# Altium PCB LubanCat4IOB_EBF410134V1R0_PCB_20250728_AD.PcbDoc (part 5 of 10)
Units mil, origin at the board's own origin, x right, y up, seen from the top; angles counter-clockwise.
Board outline 5236.21 x 4055.11 mil, 6 copper layers (TOP, GND02, ART03, PWR04, GND05, BOTTOM), stack 47.2 mil thick; 614 components, 490 nets, 2311 pads, 1916 vias.
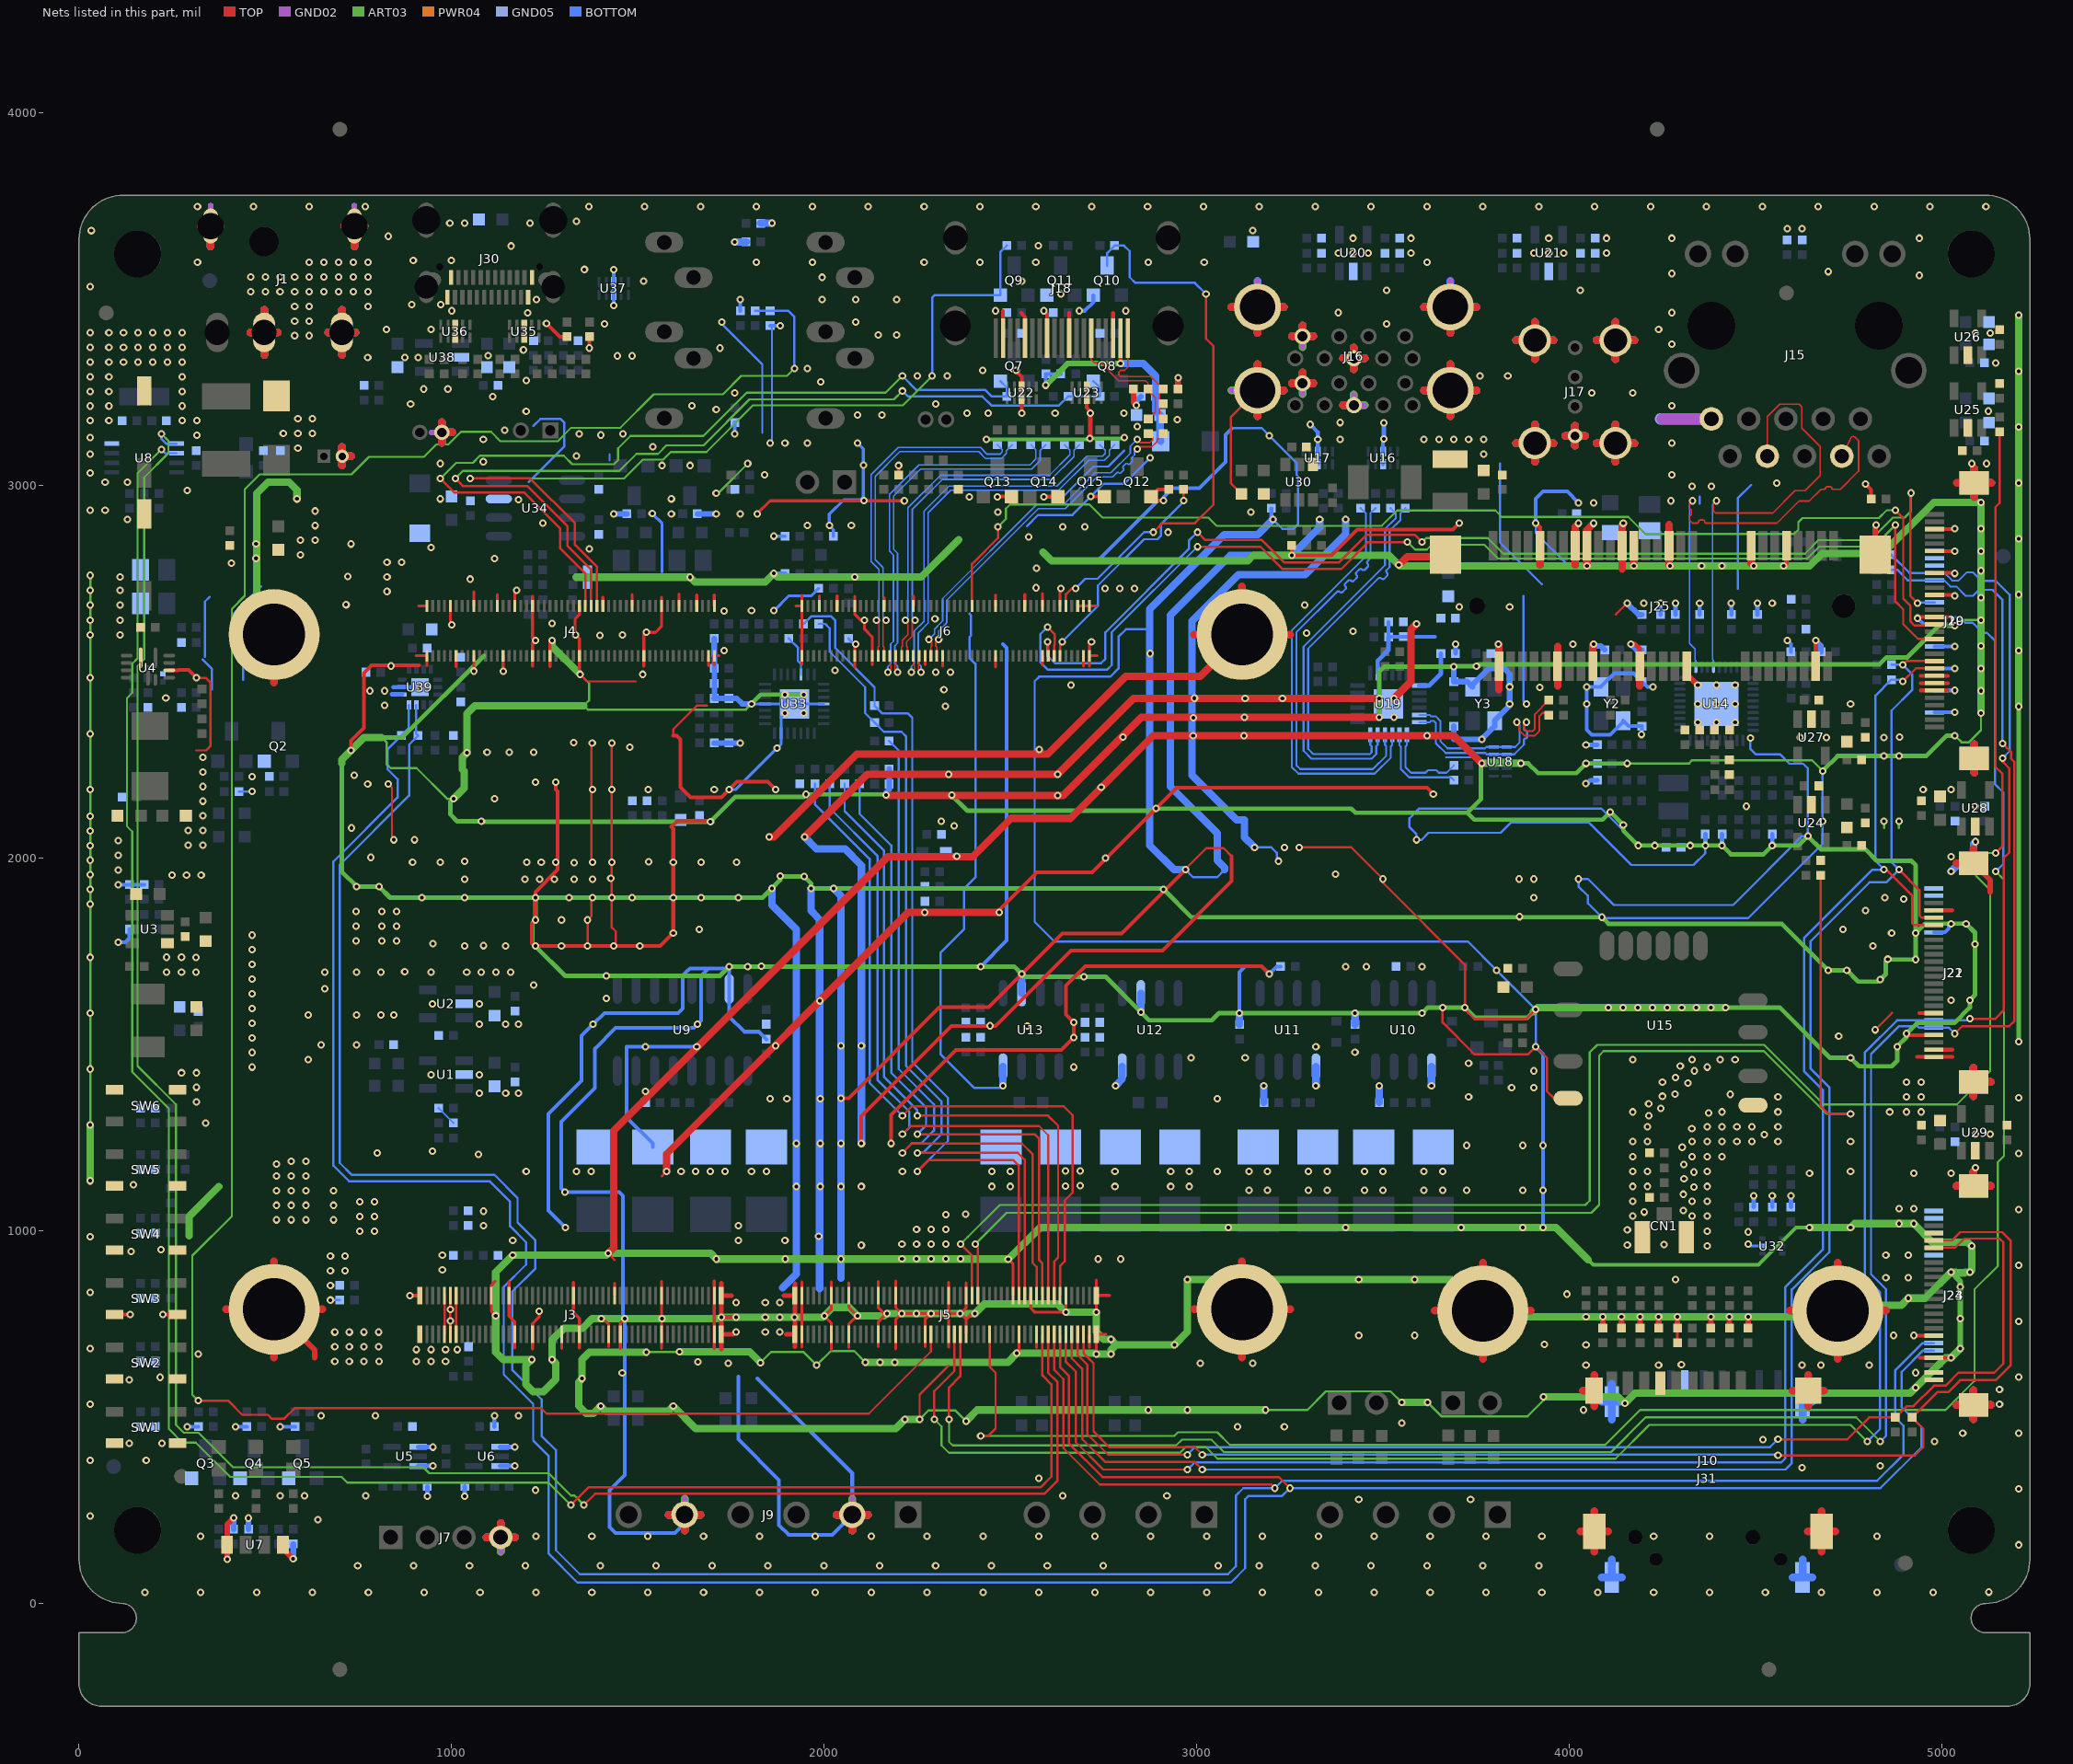
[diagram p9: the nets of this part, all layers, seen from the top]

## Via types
v1: diameter 20, hole 10, TOP to BOTTOM, 1912 vias
v2: diameter 40/50/50/50/50/40 (per signal layer), hole 0, TOP to BOTTOM, 4 vias

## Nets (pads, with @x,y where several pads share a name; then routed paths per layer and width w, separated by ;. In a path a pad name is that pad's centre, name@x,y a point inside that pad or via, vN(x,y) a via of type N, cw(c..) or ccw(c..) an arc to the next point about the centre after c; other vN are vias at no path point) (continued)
GND: (continued)
  BOTTOM w12: 839.68,2439.68 U39.8@867.36,2439.68 ; 844,2459.37 U39.9@867.36,2459.37 v1(915,2459.37) ; U5.3@910.43,369.09 949.72,369.09 v1(950,369.37) ; U5.1@910.43,420.28 949.09,420.28 v1(950,419.37) ; v1(934.68,287.57) Z3.2@934.68,314.37 ; v1(1035.32,287.57) Z4.2@1035.32,314.37 ; C42.2@1114.68,474.37 1114.68,504.05 v1(1115,504.37) ; U6.3@1130.43,369.09 1169.72,369.09 v1(1170,369.37) ; U6.1@1130.43,420.28 1169.41,420.28 v1(1170,419.69) ; v1(3502,3125.37) v1(3502,3168.37) ; v1@3620,534.07 v1(3620,539.37) ; C112.2@3694.68,2549.37 3694.68,2574.05 v1(3695,2574.37) ; v1(4044,2200.37) 4047,2200.37 4056,2209.37 R103.2@4075.32,2209.37 ; v1(4045,2254.37) R102.2@4075.32,2254.37 ; v1(4045,2304.37) R98.2@4075.32,2304.37 ; R86.2@4245,2654.05 v1(4245,2684.37) ; C88.2@4285,2654.05 v1(4285,2684.37) ; C84.2@4350,2654.05 v1(4350,2684.37) ; v1(4365,2034.37) R83.2@4365,2064.69 ; v1(4410,2034.37) R92.2@4410,2064.69 ; C83.2@4435,2654.05 v1(4435,2684.37) ; C155.2@4495,1064.05 v1(4495,1094.37) ; C89.2@4505,2654.05 v1(4505,2684.37) ; C153.2@4545,1064.05 v1(4545,1094.37) ; v1(4545,2034.37) R91.2@4545,2064.69 ; C154.2@4595,1064.05 v1(4595,1094.37)
  BOTTOM w15: C48.2@415,199.05 v1(415,229.37) ; C47.2@455,199.05 v1(455,229.15) ; v1(575,119.37) C46.2@575,159.69 ; v1(1435,2924.37) R215.1@1470.32,2924.37 ; R211.1@1659.68,2924.37 v1(1710,2924.37) ; C169.2@1705,2309.69 C168.2@1745,2309.69 1774.68,2309.69 v1(1775,2309.37) ; R234.1@1705,2589.69 1705,2544.37 1705.32,2544.05 C180.2@1705.32,2509.37 C181.2@1705.32,2469.37 1705.32,2429.37 C167.2@1705,2429.05 C166.2@1745,2429.05 1765.32,2429.05 1780,2414.37 v1(1805,2414.37) ; v1(2166,2169.37) 2166,2175.37 2174.68,2184.05 C174.2@2174.68,2199.37 C175.2@2174.68,2239.37 ; v1(2838,3215.37) 2838,3227.05 D34.1@2850.32,3239.37 ; C102.1@3690,2354.69 3690,2319.37 v1(3765,2319.37) 3799.53,2353.9 Y3.2@3799.53,2369.09 3840,2409.57 v1(3840,2414.37) v1(3840,2460.37) 3840,2494.37 3825,2509.37 3784.88,2509.37 3740.47,2464.96 Y3.4@3740.47,2459.65 3726.07,2474.05 C103.2@3690,2474.05 v1(3690,2514.37) ; v1(4065,2574.37) 4070,2569.37 4085.32,2569.37 C86.2@4095.32,2559.37 ; v1(4155,2684.37) 4185.32,2654.05 C160.2@4195,2654.05 ; v1(4165,2574.37) 4180.32,2559.05 C85.2@4195,2559.05 ; v1(4661.56,2584.37) 4675.32,2570.61 C158.2@4675.32,2554.37
  BOTTOM w20: v1(1760,3654.37) R219.2@1790.32,3654.37 ; R217.2@1829.68,3704.37 v1(1860,3704.37) ; v1(1860,1919.37) 1860,1874.37 1925,1809.37 v1(1925,1234.37) v1(1925,1119.37) 1925,884.37 1888,847.37 ; v1(1947.5,2056.87) 1979.05,2025.32 2055.85,2025.32 2100,1981.17 v1(2100,1496.37) v1(2100,1234.37) ; v1(1965,1919.37) 1965,1859.37 1980,1844.37 1980,1843.18 1987.8,1835.38 1987.8,844.37 ; v1(2025,1919.37) 2045,1899.37 v1(2045,1496.37) v1(2045,1356.37) v1(2045,1234.37) v1(2045,1119.37) v1(2045,924.37) 2045,872.65 ; v1(2480,1389.37) U13.8@2480,1440.94 ; U13.2@2530,1637.8 v1(2530,1689.37) ; v1(2782.31,1389.37) 2800,1407.06 U12.8@2800,1440.94 ; v1(2850,1587.36) U12.2@2850,1637.8 ; v1(2970,1969.37) 2939,1969.37 2874,2034.37 2874,2614.37 2874,2668.37 3074,2868.37 3164,2868.37 v1(3205,2909.37) ; 3075,1969.37 3075,1974.37 3055,1994.37 3055,2067.14 2929.65,2192.49 2929.65,2652.25 3090.29,2812.89 v1(3255,2812.89) 3330,2887.89 v1(3330,2909.37) ; C61.2@3115,1554.05 v1(3115,1584.37) ; v1(3155,2029.37) 3128.05,2056.32 3128.05,2103.37 3107.38,2103.37 2987.65,2223.1 2987.65,2636.02 3112.35,2760.72 3291.35,2760.72 3400,2869.37 v1(3400,2909.37) ; R72.2@3180.32,1344.37 v1(3180.32,1389.37) ; v1(3320,1389.37) U11.5@3320,1440.94 ; C60.2@3425,1554.05 v1(3425,1584.37) ; R64.2@3490.32,1344.37 v1(3490.32,1389.37) ; v1@3589.68,2629.05 v1(3590,2629.37) ; v1(3630,1389.37) U10.5@3630,1440.94 ; 4280.24,3179.13 J15.10@4381.49,3179.13 ; v1(5025,1964.37) 5046.85,1986.22 J21.25@5084.99,1986.22 5084.99,2039.36 v1(5090,2044.37)
  BOTTOM w21: 326.66,3696.82 J1.1@353.36,3696.82 ; 353.36,3642.57 J1.1@353.36,3696.82 ; 380.06,3696.82 J1.1@353.36,3696.82 ; 414.1,789.42 SS2.1@523.46,789.42 ; 460.53,3411.32 J1.2@497.06,3411.32 ; 497.06,3351.17 J1.2@497.06,3411.32 ; 497.06,3471.47 J1.2@497.06,3411.32 ; 523.46,680.06 SS2.1@523.46,789.42 ; 523.46,898.79 SS2.1@523.46,789.42 ; 523.46,2491.08 SS1.1@523.46,2600.44 523.46,2709.81 ; 533.59,3411.32 J1.2@497.06,3411.32 ; 669.13,3411.32 J1.3@705.66,3411.32 ; 705.66,3351.17 J1.3@705.66,3411.32 ; 705.66,3471.47 J1.3@705.66,3411.32 ; 706.26,3054.25 J8.2@706.26,3078.97 ; 706.26,3103.69 J8.2@706.26,3078.97 ; 712.46,3696.82 J1.5@739.16,3696.82 ; 730.98,3078.97 J8.2@706.26,3078.97 ; 739.16,3642.57 J1.5@739.16,3696.82 ; 742.19,3411.32 J1.3@705.66,3411.32 ; 765.87,3696.82 J1.5@739.16,3696.82 ; 974.06,3115.23 J2.2@974.06,3142.9 ; 974.06,3170.57 J2.2@974.06,3142.9 ; 1001.73,3142.9 J2.2@974.06,3142.9 ; 1093.39,177.48 J7.4@1131.89,177.48 ; 1131.89,138.98 J7.4@1131.89,177.48 ; 1131.89,215.98 J7.4@1131.89,177.48 ; 1170.39,177.48 J7.4@1131.89,177.48 ; 1582.95,238.19 J9.5@1625.39,238.19 ; 1625.39,280.62 J9.5@1625.39,238.19 ; 1667.83,238.19 J9.5@1625.39,238.19 ; 2032.95,238.19 J9.2@2075.39,238.19 ; 2075.39,195.75 J9.2@2075.39,238.19 ; 2117.82,238.19 J9.2@2075.39,238.19 ; 3012.53,789.42 SS3.1@3121.89,789.42 ; 3012.53,2600.44 SS4.1@3121.89,2600.44 ; 3121.89,680.06 SS3.1@3121.89,789.42 ; 3121.89,898.79 SS3.1@3121.89,789.42 ; 3121.89,2491.08 SS4.1@3121.89,2600.44 ; 3121.89,2709.81 SS4.1@3121.89,2600.44 ; J16.20@3163.19,3255.96 3233.19,3255.96 ; 3163.19,3409.56 J16.19@3163.19,3479.56 ; 3163.19,3549.56 J16.19@3163.19,3479.56 ; 3231.25,789.42 SS3.1@3121.89,789.42 ; 3231.25,2600.44 SS4.1@3121.89,2600.44 ; 3233.19,3479.56 J16.19@3163.19,3479.56 ; 3255.44,3274.86 J16.13@3284.09,3274.86 ; 3255.44,3400.86 J16.4@3284.09,3400.86 ; 3284.09,3429.51 J16.4@3284.09,3400.86 ; 3312.75,3400.86 J16.4@3284.09,3400.86 ; 3393.24,3215.76 J16.16@3421.89,3215.76 ; 3393.24,3341.76 J16.7@3421.89,3341.76 ; 3421.89,3244.42 J16.16@3421.89,3215.76 ; 3421.89,3370.42 J16.7@3421.89,3341.76 ; 3450.55,3215.76 J16.16@3421.89,3215.76 ; 3450.55,3341.76 J16.7@3421.89,3341.76 ; 3610.59,3255.96 J16.21@3680.59,3255.96 3750.59,3255.96 ; 3610.59,3479.56 J16.22@3680.59,3479.56 ; 3658.48,785.48 SS6.1@3767.85,785.48 ; 3680.59,3409.56 J16.22@3680.59,3479.56 ; 3680.59,3549.56 J16.22@3680.59,3479.56 ; 3750.59,3479.56 J16.22@3680.59,3479.56 ; 3767.85,676.12 SS6.1@3767.85,785.48 ; 3767.85,894.85 SS6.1@3767.85,785.48 ; 3857.12,3114.17 J17.8@3907.43,3114.17 ; 3857.12,3389.76 J17.7@3907.43,3389.76 ; 3877.21,785.48 SS6.1@3767.85,785.48 ; 3907.43,3063.86 J17.8@3907.43,3114.17 ; 3907.43,3164.47 J17.8@3907.43,3114.17 ; 3907.43,3440.07 J17.7@3907.43,3389.76 ; 3957.74,3114.17 J17.8@3907.43,3114.17 ; 3957.74,3389.76 J17.7@3907.43,3389.76 ; 3989.05,3133.69 J17.4@4015.74,3133.69 ; 4015.74,3107.01 J17.4@4015.74,3133.69 ; 4015.74,3160.38 J17.4@4015.74,3133.69 ; 4042.43,3133.69 J17.4@4015.74,3133.69 ; 4073.66,3114.17 J17.5@4123.97,3114.17 ; 4073.66,3389.76 J17.6@4123.97,3389.76 ; 4087.48,69.48 J31.11@4114.16,69.48 ; 4087.48,541.92 J31.9@4114.16,541.92 ; 4114.16,117.82 J31.11@4114.16,69.48 ; 4114.16,493.58 J31.9@4114.16,541.92 ; 4114.16,590.26 J31.9@4114.16,541.92 ; 4123.97,3063.86 J17.5@4123.97,3114.17 ; 4123.97,3164.47 J17.5@4123.97,3114.17 ; 4123.97,3339.45 J17.6@4123.97,3389.76 ; 4123.97,3440.07 J17.6@4123.97,3389.76 ; 4140.85,69.48 J31.11@4114.16,69.48 ; v1@4140.85,541.92 J31.9@4114.16,541.92 ; 4174.28,3114.17 J17.5@4123.97,3114.17 ; 4174.28,3389.76 J17.6@4123.97,3389.76 ; 4599.29,69.48 J31.10@4625.98,69.48 ; 4625.98,117.82 J31.10@4625.98,69.48 ; 4625.98,493.58 J31.8@4625.98,541.92 ; 4625.98,590.26 J31.8@4625.98,541.92 ; 4652.66,69.48 J31.10@4625.98,69.48 ; 4652.66,541.92 J31.8@4625.98,541.92 ; 4720.61,676.12 SS5.1@4720.61,785.48 4720.61,894.85 ; 5038.62,533.46 J23.26@5084.99,533.46 ; 5038.62,1120.08 J23.25@5084.99,1120.08 ; 5084.99,494.97 J23.26@5084.99,533.46 ; 5084.99,571.96 J23.26@5084.99,533.46 ; 5084.99,1158.57 J23.25@5084.99,1120.08 ; 5084.99,1361.11 J21.26@5084.99,1399.6 ; 5084.99,1438.1 J21.26@5084.99,1399.6 ; 5086.92,2229.01 J19.31@5086.92,2267.5 5086.92,2306 ; 5086.92,2969.16 J19.32@5086.92,3007.66 ; 5086.92,3046.16 J19.32@5086.92,3007.66 ; 5131.36,533.46 J23.26@5084.99,533.46 ; 5131.36,1120.08 J23.25@5084.99,1120.08 ; 5131.36,1399.6 J21.26@5084.99,1399.6 ; 5133.29,3007.66 J19.32@5086.92,3007.66
  other v1: 176.43,30 326.43,30 476.43,30 626.43,30 776.43,30 926.43,30 1076.43,30 1226.43,30 1376.43,30 1526.43,30 1676.43,30 1826.43,30 1976.43,30 2126.43,30 2276.43,30 2426.43,30 2576.43,30 2726.43,30 2876.43,30 3026.43,30 3176.43,30 3326.43,30 3476.43,30 3626.43,30 3776.43,30 3926.43,30 4076.43,30 4226.43,30 4376.43,30 4526.43,30 4676.43,30 4826.43,30 4976.43,30 5126.43,30.39 748,101.37 898,101.37 1048,101.37 1198,101.37 1399,101.37 1549,101.37 1699,101.37 1849,101.37 1999,101.37 2149,101.37 2299,101.37 2449,101.37 2599,101.37 2749,101.37 3058,101.37 3168,101.37 3318,101.37 3468,101.37 3618,101.37 3768,101.37 3918,101.37 5206.21,157.42 326.43,180 1226.43,180 1376.43,180 1526.43,180 1676.43,180 1826.43,180 1976.43,180 2126.43,180 2276.43,180 2426.43,180 2576.43,180 2726.43,180 2876.43,180 3026.43,180 3176.43,180 3326.43,180 3476.43,180 3626.43,180 3776.43,180 3926.43,180 4226.43,180 4376.43,180 4826.43,180 640.63,224.37 30,234.32 3435,279.37 3735,279.37 420,289.37 540,289.37 605,289.37 770,289.37 2640,289.37 2920,289.37 1225,304.37 5206.21,307.42 2576,336.37 4625,364.37 4835,369.37 30,384.32 180,384.32 135,430.12 222.4,430.12 4980,434.37 4520,439.37 5056.21,457.42 5206.21,457.42 3110,474.37 3235,474.37 3550,484.37 650,504.37 795,504.37 1180,504.37 4038.5,519.37 30,534.33 5155,534.37 5155,574.37 135,600 218,607 5206.21,607.42 1458,618.37 4930,619.37 4045,639.37 4240,639.37 4625,639.37 4675,639.37 4805,639.37 4300.66,640.78 1743,644.37 3010,644.37 3150,644.37 1661,648.37 686.26,649.37 725.63,649.37 765,649.37 805,649.37 905.09,649.69 944.46,649.69 983.83,649.69 320,669.37 905.09,681.18 944.46,681.18 983.83,681.18 1015.32,681.18 30,684.33 686.26,688.74 725.63,688.74 765,688.74 804.37,688.74 4045,694.37 3933,695.37 3435,719.37 3585,719.37 4870,719.37 686.26,728.11 725.63,728.11 765,728.11 804.37,728.11 1842.02,728.91 1881.39,728.91 5206.21,757.42 1763.28,807.65 1842.02,807.65 1881.39,807.65 3994,830.37 30,834.33 675,853.74 4285,869.37 4850,874.37 4910,874.37 675,893.11 714.37,893.11 975.09,895.31 5206.21,907.42 2796,924.37 2208.78,925 2248.15,925 2287.52,925 2326.89,925 2366.26,925 675,932.48 714.37,932.48 4850,934.37 4910,934.37 975.09,934.68 140,945 220,950 4370,959.37 2100,961.37 4156,962.37 4254,963.37 2208.78,964.37 2248.15,964.37 2287.52,964.37 2326.89,964.37 1164.06,974.05 1770,974.37 1895,974.37 30,984.33 1985.2,985.57 4480,997.21 753.37,999.37 792.74,999.37 4370,999.37 4156,1002.37 2248.15,1003.74 2287.52,1003.74 2326.89,1003.74 1085.32,1013.42 1770,1013.74 530,1029.37 569.37,1029.37 608.74,1029.37 683,1029.37 753.37,1038.74 792.74,1038.74 4170,1039.37 4330,1039.37 4370,1039.37 2326.89,1043.11 2380,1044.37 4201,1050.37 1085.32,1052.79 4306,1054.37 5206.21,1057.42 4885,1059.37 4925,1059.37 530,1068.74 569.37,1068.74 608.74,1068.74 683,1068.74 753.37,1078.11 792.74,1078.11 4170,1079.37 4330,1079.37 4370,1079.37 4306,1098.37 530,1108.11 569.37,1108.11 608.74,1108.11 683,1108.11 3140,1109.37 3190,1109.37 3300,1109.37 3350,1109.37 3450,1109.37 3500,1109.37 3610,1109.37 3660,1109.37 3725,1109.37 3875,1109.37 4334.4,1117.77 1990,1119.37 2100,1119.37 2450,1119.37 2500,1119.37 2780.54,1119.37 2930,1119.37 2980,1119.37 4170,1119.37 4210,1119.37 4370,1119.37 2647.6,1120.37 2686.97,1121 146,1124 4308,1139.37 530,1147.48 569.37,1147.48 608.74,1147.48 4645,1154.37 4925,1154.37 5025,1154.37 4334.4,1157.77 1200,1159.37 1335,1159.37 1375,1159.37 1616.03,1159.37 1655.4,1159.37 1694.77,1159.37 1734.14,1159.37 1805,1159.37 1845,1159.37 2210,1159.37 2450,1159.37 2500,1159.37 2780.54,1159.37 2930,1159.37 2980,1159.37 3055,1159.37 3140,1159.37 3190,1159.37 3300,1159.37 3350,1159.37 3450,1159.37 3500,1159.37 3610,1159.37 3660,1159.37 4170,1159.37 4210,1159.37 4370,1159.37 4755,1159.37 2647.6,1160.37 2686.97,1160.37 5090,1169.37 4307,1178.37 530,1179.37 569.37,1186.85 608.74,1186.85 4170,1199.37 4330,1199.37 4370,1199.37 4410,1199.37 1072,1205.37 5206.21,1207.42 800,1209.37 949,1214.37 4303,1224.37 3725,1229.37 3875,1229.37 1990,1234.37 4170,1239.37 4210,1239.37 4330,1239.37 4370,1239.37 4410,1239.37 4450,1239.37 4490,1239.37 4560,1239.37 4755,1239.37 4523,1258.37 5090,1259.37 5130,1259.37 4329,1274.37 4210,1279.37 4370,1279.37 4410,1279.37 4450,1279.37 4490,1279.37 4560,1279.37 340,1289.37 4214,1309.37 4374,1316.37 4170,1319.37 4410,1319.37 4560,1319.37 4860,1319.37 4905,1319.37 4945,1319.37 4246,1328.37 4213,1341.37 315,1345.63 1855,1354.37 1900,1354.37 1990,1354.37 3055,1354.37 5206.21,1357.42 3730,1359.37 4560,1359.37 4905,1359.37 4945,1359.37 4250,1361.37 4432,1366.37 4284,1367.37 1075,1369.37 1145.5,1369.37 1180,1369.37 3845,1384.37 3905,1384.37 315,1385 4318.8,1396.97 4250,1399.37 4905,1399.37 4945,1399.37 4285,1411.37 945,1419.37 1075,1419.37 275,1424.37 315,1424.37 3905,1429.37 4336,1429.37 465,1439.37 2670,1439.37 4370,1439.37 4298,1442.37 3730,1449.37 615,1459.37 4170,1459.37 4330,1459.37 4405,1459.37 4445,1459.37 2985,1464.37 3130,1464.37 465,1478.74 3425,1479.37 3320,1494.37 1870,1497.17 650,1499.37 745,1499.37 465,1518.11 4723,1522.37 2545,1549.37 2445,1550.37 1075,1554.37 1145,1554.37 1180,1554.37 465,1557.48 615,1579.37 745,1579.37 810,1579.37 845,1579.37 465,1596.85 949,1609.37 1075,1609.37 1988.4,1617.17 5025,1619.37 1415,1624.37 465,1636.22 660,1649.37 1220,1659.37 465,1675.59 235,1694.37 275,1694.37 314.37,1694.37 660,1694.37 745,1694.37 810,1694.37 945,1694.37 1040.58,1694.37 1079.95,1694.37 1119.32,1694.37 1158.69,1694.37 874,1695.37 3400,1709.37 3455,1709.37 3605,1709.37 1832,1710.77 465,1714.96 235,1734.37 275,1734.37 314.37,1733.74 465,1754.33 1035,1764.37 1145,1764.37 4815,1764.37 1086,1765.37 950,1770.37 744,1778.37 813,1778.37 852.37,1778.37 465,1793.7 4865,1799.37 1665,1809.37 4735,1809.37 744,1817.74 813,1817.74 852.37,1817.74 1295,1834.37 744,1857.11 813,1857.11 852.37,1857.11 4795,1859.37 4897.55,1890.52 3905,1894.37 4846.87,1894.37 1035,1943.57 1197.26,1943.77 1236.63,1943.77 1276,1943.77 1328.8,1943.97 1378,1944.17 3865.63,1944.37 3905,1944.37 1427.2,1945.77 249.26,1954.37 288.63,1954.37 328,1954.37 3373,1957.37 105,1968.42 1329,1987.97 895,1989.37 970,1989.37 1201.26,1989.37 1240.63,1989.37 1280,1989.37 1670,1989.37 1765,1989.37 1529,1990.97 1035,1991.97 2755.6,2000.17 783,2002.37 5025,2004.37 2355.8,2004.97 105,2007.79 3235.63,2029.37 293.11,2035 332.48,2035 105,2047.16 293.11,2074.37 332.48,2074.37 731,2081.37 2349,2086.97 2314.69,2099.37 332.48,2113.74 4475,2139.37 332.48,2153.11 1115,2159.37 1705,2184.37 4950,2184.37 5024.8,2184.37 1528,2184.57 2743.4,2190.37 332.48,2192.48 775,2199.37 1225,2204.37 465,2218.74 738.2,2222.37 2334.4,2225.37 332.48,2231.85 332.48,2271.22 1095,2284.37 1155,2284.37 1220,2284.37 2577.4,2292.37 1478.2,2298.57 1328,2310.17 4620,2324.37 4690,2324.37 4845,2324.37 2801.8,2325.17 4887,2325.57 2990.4,2328.97 4345,2364.37 4395,2364.37 4445,2364.37 3529.37,2378.47 1945,2389.37 2325,2407.97 819.74,2410 4345,2414.37 4395,2414.37 4445,2414.37 4755,2414.37 233,2430.37 2994,2429.57 780.37,2449.37 819.74,2449.37 2321.2,2452.77 3921.2,2458.57 4395,2464.37 4445,2464.37 2662.74,2464.72 1512.57,2493.74 2299.61,2499.43 2338.98,2499.43 1059.8,2502.37 2028.71,2503.88 837,2516 2875,2549.37 1731.4,2556.97 4010,2574.37 1398,2598.37 110,2599.32 1459,2599.37 3294.6,2604.77 3420,2609.37 1270,2630 110,2639.32 2297.6,2642.17 1731,2663.37 1805,2664.37 3705,2674.37 3840,2674.37 110,2679.32 3290,2679.37 717,2680.37 4200,2684.37 4545,2684.37 826.89,2716.08 110,2719.32 2753.74,2724.37 2793.11,2724.37 2832.48,2724.37 2569,2726 1050,2749.37 110,2754.67 826.89,2755.45 721,2756.37 2570,2778.77 409,2792.37 826.89,2794.82 866.26,2794.82 1115,2804.37 475,2805 593.89,2814 1370,2830.37 945,2834.19 730,2843.37 475,2844.37 593.89,2853.37 633.26,2853.37 2549,2862 2923.43,2875.31 2640,2889.37 2700,2889.37 633.26,2892.74 1954.87,2892.86 2072.97,2892.86 1245,2899.37 4025,2898.95 130,2909.37 1590,2924.37 1775,2924.37 2466.68,2929.37 3145,2929.37 633.26,2932.11 30,2934.32 70,2934.37 4065,2953.95 4273,2959.37 2107,2960.37 1180,2962.13 969.25,2964.37 1590,2964.37 2390,2969.37 290,2987 4330,2998.37 4381,2998.37 4557,3007.37 70,3009.37 130,3009.37 1840,3029.37 4275,3029.37 30,3034.37 1565,3054.37 1640,3054.37 2106,3055.37 970,3059.37 5080,3059.37 5120,3059.37 1085,3064.37 1335,3079.37 30,3084.32 3770,3084.37 587.37,3101 1540,3104.37 1895,3114.37 1955,3114.37 4275,3114.37 1085,3124.37 3385,3124.37 3610,3124.37 3650,3124.37 3690,3124.37 3730,3124.37 3770,3124.37 30,3129.37 316.22,3135 1401,3135.97 1342.5,3139.37 1460,3139.37 548,3140.37 587.37,3140.37 626.74,3140.37 1142.46,3149.37 2840,3158.62 3385,3169.37 30,3174.37 80,3174.37 276.85,3174.37 316.22,3174.37 2948.2,3177.57 587.37,3179.74 626.74,3179.74 2090,3189.37 2155,3189.37 2383,3194.37 2440,3194.37 2620,3194.37 2805,3194.37 5125,3200.12 1710,3204.37 30,3213.74 80,3213.74 276.85,3213.74 4275,3214.37 890,3219.37 2300,3219.37 1110,3239.37 1760,3249.37 4060,3249.37 4170,3249.37 30,3253.11 80,3253.11 276.85,3253.11 925,3259.37 990,3259.37 1991,3278.37 1201,3282.37 30,3292.48 80,3292.48 276.85,3292.48 2250,3294.37 2330,3294.37 3760,3294.37 3835,3294.37 2425,3309.37 1955,3314.37 5145,3329.37 30,3331.85 80,3331.85 119.37,3331.85 158.74,3331.85 198.11,3331.85 237.48,3331.85 276.85,3331.85 775,3344.37 875,3344.37 910,3344.37 1445,3348.37 1485,3348.37 1097.8,3349.12 1192.59,3364.37 1720,3369.37 30,3371.22 80,3371.22 119.37,3371.22 158.74,3371.22 198.11,3371.22 237.48,3371.22 276.85,3371.22 4275,3379.37 578.73,3402.67 618.1,3402.67 2145,3404.37 2195,3404.37 5090,3409.37 5130,3409.37 30,3410.59 80,3410.59 119.37,3410.59 158.74,3410.59 198.11,3410.59 237.48,3410.59 276.85,3410.59 825,3419.37 945,3419.37 4240,3419.37 1410,3434.37 3510,3434.37 2085,3439.37 578.73,3442.04 618.1,3442.04 1204.06,3463.43 3380,3464.37 4275,3464.37 1000,3469.37 2460,3469.37 2810,3469.37 578.73,3481.41 618.1,3481.41 775.58,3481.41 893,3486.37 971,3486.37 1227.75,3499.37 1995,3499.37 2085,3499.37 2195,3499.37 2635,3514.37 460.62,3520.78 499.99,3520.78 539.36,3520.78 578.73,3520.78 618.1,3520.78 657.47,3520.78 696.84,3520.78 736.21,3520.78 775.58,3520.78 3510,3524.37 4030,3524.37 30,3534.32 1515,3549.37 2530,3549.37 1995,3559.37 460.62,3560.15 499.99,3560.15 539.36,3560.15 578.73,3560.15 618.1,3560.15 657.47,3560.15 696.84,3560.15 736.21,3560.15 775.58,3560.15 4940,3564.37 4275,3569.37 4695,3574.37 1356.65,3580.37 2870,3599.37 3020,3599.37 318.1,3599.52 618.1,3599.52 657.47,3599.52 696.84,3599.52 736.21,3599.52 775.58,3599.52 1818.1,3599.52 1968.1,3599.52 2268.1,3599.52 2418.1,3599.52 2568.1,3599.52 3618.1,3599.52 897.28,3604.37 998.82,3604.37 3380,3624.37 3420,3624.37 3460,3624.37 3575,3624.37 3905,3624.37 3945,3624.37 3985,3624.37 4100,3624.37 1160,3643.37 2575,3644.37 3420,3664.37 3575,3664.37 3945,3664.37 4100,3664.37 4275,3664.37 4940,3664.37 830,3669.37 33.02,3684.29 3150,3684.37 4585,3689.37 4625,3689.37 995,3704.37 1035,3704.37 1210,3704.37 1335,3709.37 318.1,3749.52 468.1,3749.52 618.1,3749.52 768.1,3749.52 1368.1,3749.52 1518.1,3749.52 1668.1,3749.52 1818.1,3749.52 1968.1,3749.52 2118.1,3749.52 2268.1,3749.52 2418.1,3749.52 2568.1,3749.52 2718.1,3749.52 2868.1,3749.52 3018.1,3749.52 3168.1,3749.52 3318.1,3749.52 3468.1,3749.52 3618.1,3749.52 3768.1,3749.52 3918.1,3749.52 4068.1,3749.52 4218.1,3749.52 4368.1,3749.52 4518.1,3749.52 4668.1,3749.52 4818.1,3749.52 4968.1,3749.52 5118.1,3749.52
HDMI0_TX_ON: J6.89 R145.1 | length 604.8
  TOP w6: J6.89@2633.06,2543.51 2633.06,2575.69 v1(2638.74,2581.37) ; v1(2965,2960.37) R145.1@2965,2989.69
  BOTTOM w6: v1(2638.74,2581.37) 2734.74,2677.37 2734.74,2732.24 2858.8,2856.31 2894.93,2856.31 2904.43,2865.8 2904.43,2896.8 2965,2957.37 v1(2965,2960.37)
HDMI_5V: C124.1 D28.1 D34.2 J18.18 R128.1 R131.1 | length 651.6
  TOP w11: v1(2795.27,3327.56) J18.18@2795.27,3395.56
  ART03 w15: v1(2595,3269.37) 2653.19,3327.56 v1(2795.27,3327.56)
  BOTTOM w10: v1(2595,3269.37) R128.1@2595,3299.69 R131.1@2635,3299.69
  BOTTOM w20: v1(2795.27,3327.56) 2856.81,3327.56 2889.68,3294.69 D34.2@2889.68,3239.37 2889.68,3201.19 C124.1@2901.5,3189.37 2901.5,3120.94 D28.1@2903.07,3119.37
HDMI_EARC+: C121.2 D32.2 J18.14 | length 347.8
  TOP w4.2: J18.14@2716.53,3395.56 2716.53,3338.84 2725,3330.37 2742.03,3330.37 2790.56,3281.84 2862.52,3281.84 2869.68,3274.69 D32.2@2869.68,3259.37 2869.68,3254.69 2888.8,3235.57 2888.8,3197.85 C121.2@2870,3179.05
HDMI_EARC-: C122.2 D29.2 J18.19 R139.2 | length 347.1
  TOP w4.2: J18.19@2814.96,3395.56 2814.96,3317.93 2806.4,3309.37 2795.2,3309.37 2791,3305.17 2791,3297.24 2795.2,3293.05 2876.64,3293.05 D29.2@2910.32,3259.37 2900,3249.05 2900,3229.69 R139.2@2910.32,3219.37 2900,3209.05 2900,3189.05 C122.2@2910,3179.05
HDMI_TX0_CEC_M0: J4.60 Q9.2 R132.2 | length 2467.3
  TOP w6.16: v1(1050,3019.37) 1210.68,3019.37 1331.05,2899 1331.05,2841.32 1390.24,2782.13 J4.60@1390.24,2677.37
  ART03 w5.5: v1(1050,3019.37) 1463,3019.37 1513.75,3070.12 1567.75,3070.12 1588,3090.37 1684,3090.37 1809,3215.37 2211,3215.37 v1(2290,3294.37)
  BOTTOM w6: v1(2290,3294.37) 2290,3504.87 2296,3510.87 Q9.2@2472.5,3510.87 2472.5,3626.55 R132.2@2490.32,3644.37
HDMI_TX0_D0N: C118.1 J6.37 | length 936.3
  TOP w4.2: J6.37@2223.61,2543.51 2223.61,2567.06 2221.34,2569.33 2221.34,2580.71 2236.34,2595.71 2236.34,2631.97 v1(2243.74,2639.37)
  BOTTOM w4.2: v1(2243.74,2639.37) 2236.34,2646.77 2236.34,2935.83 2317.31,3016.8 2609.27,3016.8 2670.75,3078.28 2670.75,3095.44 C118.1@2685,3109.69
HDMI_TX0_D0P: C117.1 J6.35 | length 936.5
  TOP w4.2: J6.35@2207.87,2543.51 2207.87,2567.06 2210.14,2569.33 2210.14,2585.35 2225.14,2600.35 2225.14,2631.97 v1(2217.74,2639.37)
  BOTTOM w4.2: v1(2217.74,2639.37) 2225.14,2646.77 2225.14,2940.47 2312.67,3028 2604.63,3028 2659.55,3082.92 2659.55,3095.14 C117.1@2645,3109.69
HDMI_TX0_D1N: C115.1 J6.33 | length 1012.4
  TOP w4.2: J6.33@2192.12,2543.51 2192.12,2519.97 2190.35,2518.2 2190.35,2506.32 v1(2197.24,2499.43)
  BOTTOM w4.2: v1(2197.24,2499.43) 2197.24,2515.06 2189.84,2522.46 2189.84,2570.38 2197.1,2577.63 2197.1,2818.55 2186.5,2829.15 2186.5,2972.39 2258.91,3044.8 2557.31,3044.8 2579.6,3067.09 2579.6,3094.29 C115.1@2595,3109.69
HDMI_TX0_D1P: C114.1 J6.31 | length 1012.4
  TOP w4.2: v1(2171.24,2499.43) 2179.15,2507.34 2179.15,2517.19 2176.37,2519.97 J6.31@2176.37,2543.51
  BOTTOM w4.2: v1(2171.24,2499.43) 2171.24,2515.06 2178.64,2522.46 2178.64,2575.01 2185.9,2582.27 2185.9,2813.91 2175.3,2824.51 2175.3,2977.03 2254.27,3056 2552.67,3056 2568.4,3071.73 2568.4,3096.29 C114.1@2555,3109.69
HDMI_TX0_D2N: C116.1 J6.29 | length 919.9
  TOP w4.2: J6.29@2160.62,2543.51 2160.62,2567.06 2158.35,2569.33 2158.35,2631.97 v1(2165.75,2639.37)
  BOTTOM w4.2: v1(2165.75,2639.37) 2158.35,2646.77 2158.35,2779.9 2136.9,2801.35 2136.9,3024.79 2203.38,3091.27 2414.89,3091.27 2432.89,3073.27 2476.27,3073.27 2489.16,3086.16 2489.16,3093.84 C116.1@2505,3109.69
HDMI_TX0_D2P: C113.1 J6.27 | length 918.7
  TOP w4.2: v1(2139.75,2639.37) 2147.15,2631.97 2147.15,2569.33 2144.88,2567.06 J6.27@2144.88,2543.51
  BOTTOM w4.2: v1(2139.75,2639.37) 2147.15,2646.77 2147.15,2775.26 2125.7,2796.71 2125.7,3029.43 2198.74,3102.47 2419.53,3102.47 2437.53,3084.47 2471.63,3084.47 2477.95,3090.8 2477.95,3096.74 C113.1@2465,3109.69
HDMI_TX0_D3N: C120.1 J6.41 | length 1073.5
  TOP w4.2: J6.41@2255.11,2543.51 2255.11,2519.97 2253.34,2518.2 2253.34,2506.32 v1(2260.24,2499.43)
  BOTTOM w4.2: v1(2260.24,2499.43) 2260.24,2515.06 2252.84,2522.46 2252.84,2604.92 2279.5,2631.59 2279.5,2927.03 2339.94,2987.47 2629.31,2987.47 2710.11,3068.27 2752.18,3068.27 2765.6,3081.69 2765.6,3095.29 C120.1@2780,3109.69
HDMI_TX0_D3P: C119.1 J6.39 | length 1074.4
  TOP w4.2: v1(2234.24,2499.43) 2242.14,2507.34 2242.14,2517.19 2239.36,2519.97 J6.39@2239.36,2543.51
  BOTTOM w4.2: v1(2234.24,2499.43) 2234.24,2515.06 2241.64,2522.46 2241.64,2609.56 2268.3,2636.23 2268.3,2931.67 2335.3,2998.67 2624.67,2998.67 2705.47,3079.47 2747.54,3079.47 2754.4,3086.33 2754.4,3095.29 C119.1@2740,3109.69
HDMI_TX0_HPD_M0: J6.92 Q10.3 R133.2 | length 1502
  TOP w6: J6.92@2648.81,2677.37 2648.81,2708.18 2665,2724.37 v1(2675,2724.37) ; v1(2884.06,2875.31) 2908.13,2899.37 2995,2899.37 3045,2949.37 3045,3374.37 3025,3394.37 v1(3025,3514.37)
  BOTTOM w6: v1(2675,2724.37) 2700.63,2750 2733.63,2750 2858.94,2875.31 v1(2884.06,2875.31) ; Q10.3@2760,3590.87 2760,3624.69 R133.2@2779.68,3644.37 2805,3644.37 2820,3629.37 2820,3559.37 2835,3544.37 2995,3544.37 v1(3025,3514.37)
HDMI_TX0_SBDN: C122.1 J6.47 | length 954.5
  TOP w4.2: J6.47@2302.36,2543.51 2302.36,2567.06 2299.57,2569.84 2299.57,2579.69 v1(2307.48,2587.6) ; v1(2840,3098.37) 2846,3104.37 2879.24,3104.37 2892.59,3117.72 2892.59,3122.28 C122.1@2910,3139.69
  BOTTOM w4.2: v1(2307.48,2587.6) 2307.48,2610.61 2326.9,2630.03 2326.9,2630.27 2329.08,2632.45 2329.08,2692.48 2574.84,2938.27 2647.27,2938.27 2732.27,3023.27 2774.18,3023.27 2785.41,3034.5 cw(c2788.18,3031.72) 2790.95,3034.5 ccw(c2793.72,3037.27) 2796.5,3034.5 2802.83,3040.83 ccw(c2800.06,3043.6) 2802.83,3046.38 cw(c2805.6,3049.15) 2802.83,3051.92 2809.17,3058.26 cw(c2811.94,3055.49) 2814.71,3058.26 ccw(c2817.49,3061.03) 2820.26,3058.26 2826.59,3064.59 ccw(c2823.82,3067.36) 2826.59,3070.14 cw(c2829.36,3072.91) 2826.59,3075.68 2833.1,3082.19 2833.1,3091.47 v1(2840,3098.37)
HDMI_TX0_SBDP: C121.1 J6.45 | length 952.9
  TOP w4.2: v1(2281.48,2587.6) 2288.37,2580.71 2288.37,2568.83 2286.61,2567.06 J6.45@2286.61,2543.51 ; v1(2840,3124.37) 2840,3123.97 2848.4,3115.57 2874.6,3115.57 2881.39,3122.36 2881.39,3128.3 C121.1@2870,3139.69
  BOTTOM w4.2: v1(2281.48,2587.6) 2296.28,2602.4 2296.28,2615.25 2315.7,2634.67 2315.7,2634.91 2317.88,2637.09 2317.88,2697.12 2570.2,2949.47 2642.63,2949.47 2727.63,3034.47 2769.54,3034.47 2821.9,3086.83 2821.9,3105.73 2825,3108.83 2825,3109.37 v1(2840,3124.37)
HDMI_TX0_SCL_M0: J4.56 Q7.2 R127.2 | length 2356.3
  TOP w6: v1(970,3019.37) 1008.16,2981.21 1195.32,2981.21 1291.68,2884.85 1291.68,2831.69 1358.75,2764.62 J4.56@1358.75,2677.37
  ART03 w5.5: v1(970,3019.37) 1012,3061.37 1057,3061.37 1076,3080.37 1301,3080.37 1324,3057.37 1436,3057.37 1447,3068.37 1447,3100.37 1480,3133.37 1676.09,3133.37 1792.09,3249.37 2165,3249.37 v1(2210,3294.37)
  BOTTOM w6: v1(2210,3294.37) 2247.8,3256.57 2432.8,3256.57 2450,3239.37 R127.2@2490.32,3239.37 2490.32,3263.05 Q7.2@2472.5,3280.87
HDMI_TX0_SDA_M0: C123.2 J4.58 Q8.2 R129.2 | length 2497
  TOP w6: v1(1010,3019.37) 1030,2999.37 1202.84,2999.37 1311.36,2890.85 1311.36,2838.01 1374.49,2774.88 J4.58@1374.49,2677.37
  ART03 w5.5: v1(1010,3019.37) 1030,3039.37 1450,3039.37 1496,3085.37 1554,3085.37 1576.73,3108.1 1676.28,3108.1 1799.54,3231.37 2187,3231.37 v1(2210,3254.37)
  BOTTOM w6: v1(2210,3254.37) 2225,3239.37 2425,3239.37 2449.2,3215.17 2630.48,3215.17 R129.2@2654.68,3239.37 C123.2@2740.32,3239.37 2740.32,3263.05 Q8.2@2722.5,3280.87
HP_PLUG_IN_DET: C186.1 J5.46 R206.1 | length 6511.7
  TOP w6: v1(320,544.37) 400,544.37 438,506.37 507,506.37 518,495.37 550,495.37 579,524.37 1240,524.37 1255,509.37 2120,509.37 2286.61,675.98 J5.46@2286.61,722.26
  ART03 w5.5: v1(320,544.37) 304,560.37 304,933.37 410,1039.37 410,2669.37 445,2704.37 445,2990.37 485,3030.37 731,3030.37 778,3077.37 926,3077.37 959,3110.37 991,3110.37 1025,3144.37 1106,3144.37 1131,3119.37 1285,3119.37 1321,3155.37 1453,3155.37 1542.75,3245.12 1728.12,3245.12 1777.37,3294.37 1900,3294.37 v1(1920,3314.37)
  BOTTOM w6: R206.1@1815,3469.05 C186.1@1855,3469.05 1904,3469.05 1920,3453.05 v1(1920,3314.37)
HUB_3V3: C110.1 C111.1 C112.1 R122.1 R123.1 R126.2 U19.1 U19.20 | length 399.8
  BOTTOM w10: R122.1@3514.68,2634.37 R123.1@3514.68,2594.37 3515,2594.69 C111.1@3555,2594.69 3639.68,2594.69
  BOTTOM w12: U19.20@3485.47,2497.05 3485.47,2529.84 3514.68,2559.05 R123.1@3514.68,2594.37 ; U19.1@3597.68,2463.58 3624.21,2463.58 3655.32,2494.69 C112.1@3655.32,2549.37
HUB_DM1: R116.2 U19.11 | length 1022.8
  BOTTOM w5.3: U19.11@3485.47,2331.69 3485.47,2304.3 3481.78,2300.61 3481.78,2279.57 3469.28,2267.07 3308.11,2267.07 3286.7,2288.47 3286.7,2567.87 3505.5,2786.67 3505.5,2883.87 3534.7,2913.07 3534.7,2924.99 3531.3,2928.39 R116.2@3520,2939.69
HUB_DM2: R112.2 U19.9 | length 1137.1
  BOTTOM w5.3: R112.2@3440,2939.69 3453.85,2925.84 3453.85,2810.01 3255,2611.16 3255,2244.88 3272.8,2227.07 3477.7,2227.07 3521.15,2270.52 3521.15,2300.61 3524.84,2304.3 U19.9@3524.84,2331.69
HUB_DM3: R114.2 U19.7 | length 239.3
  BOTTOM w5.3: U19.7@3564.21,2331.69 3564.21,2304.3 3560.2,2300.29 3560.2,2244.57 3575.2,2229.57 3614.08,2229.57 3617.68,2233.17 3621.28,2236.77 3642.48,2236.77 3646.08,2233.17 3649.68,2229.57 3670.52,2229.57 R114.2@3690.32,2249.37
HUB_DM4: R182.2 U18.5 U18.6 U19.5 | length 562.8
  TOP w5.3: v1(3859,2365.39) 3865.09,2359.3 3865.09,2344.03 3879.76,2329.37 3907.49,2329.37 3920,2341.88 3920,2381.66 3928.44,2390.1 3939.59,2390.1 R182.2@3945.32,2384.37
  BOTTOM w5.3: U19.5@3597.68,2384.84 3625.07,2384.84 3628.76,2381.15 3641.36,2381.15 3653.86,2368.64 3653.86,2314.37 3673.18,2295.05 3773.68,2295.05 3777.37,2298.74 U18.5@3797.78,2298.74 U18.6@3832.22,2298.74 3854.66,2298.74 3866.1,2310.18 3866.1,2358.29 v1(3859,2365.39)
HUB_DP1: R117.2 U19.12 | length 994.9
  BOTTOM w5.3: U19.12@3465.79,2331.69 3465.79,2304.3 3469.48,2300.61 3469.48,2284.67 3464.18,2279.37 3313.2,2279.37 3299,2293.57 3299,2562.78 3487.12,2750.9 cw(c3491.32,2746.7) 3495.52,2750.9 ccw(c3499.72,2755.1) 3503.93,2750.9 3510.51,2757.49 ccw(c3506.31,2761.69) 3510.51,2765.89 cw(c3514.72,2770.09) 3510.51,2774.29 3517.8,2781.57 3517.8,2878.77 3547,2907.97 3547,2926.69 R117.2@3560,2939.69
HUB_DP2: R113.2 U19.10 | length 1134.2
  BOTTOM w5.3: R113.2@3480,2939.69 3466.15,2925.84 3466.15,2804.92 3458.86,2797.64 ccw(c3462.76,2793.74) 3458.87,2789.84 cw(c3454.97,2785.93) 3458.86,2782.04 3451.67,2774.84 cw(c3447.77,2778.74) 3443.87,2774.84 ccw(c3439.97,2770.95) 3436.07,2774.84 3428.88,2767.65 ccw(c3432.78,2763.75) 3428.88,2759.85 cw(c3424.98,2755.95) 3428.88,2752.05 3421.69,2744.86 cw(c3417.79,2748.76) 3413.89,2744.86 ccw(c3409.99,2740.96) 3406.09,2744.86 3398.9,2737.67 ccw(c3402.8,2733.77) 3398.9,2729.87 cw(c3395,2725.97) 3398.9,2722.07 3391.71,2714.88 cw(c3387.81,2718.78) 3383.91,2714.88 ccw(c3380.01,2710.98) 3376.11,2714.88 3267.3,2606.07 3267.3,2249.97 3277.9,2239.37 3472.61,2239.37 3508.85,2275.61 3508.85,2300.61 3505.16,2304.3 U19.10@3505.16,2331.69
HUB_DP3: R115.2 U19.8 | length 248.5
  BOTTOM w5.3: U19.8@3544.53,2331.69 3544.53,2302.64 3547.9,2299.27 3547.9,2239.47 3570.1,2217.27 3682.42,2217.27 R115.2@3690.32,2209.37
HUB_DP4: R183.2 U18.4 U18.7 U19.6 | length 582.9
  TOP w5.3: v1(3885,2365.39) 3877.39,2357.78 3877.39,2349.13 3884.85,2341.67 3902.4,2341.67 3907.7,2346.97 3907.7,2386.75 R183.2@3945.32,2424.37
  BOTTOM w5.3: U19.6@3597.68,2365.16 3625.07,2365.16 3628.76,2368.85 3636.26,2368.85 3641.56,2363.55 3641.56,2309.28 3668.09,2282.74 3774.62,2282.74 3778.32,2279.05 U18.4@3797.78,2279.05 U18.7@3832.22,2279.05 3852.36,2279.05 3878.4,2305.09 3878.4,2317.43 cw(c3882.7,2317.43) 3882.7,2321.74 ccw(c3882.7,2326.03) 3887,2326.03 3887,2338.64 ccw(c3882.7,2338.64) 3882.7,2342.94 cw(c3882.7,2347.24) 3878.4,2347.24 3878.4,2358.41 3885,2365.01 v1(3885,2365.39)
I2C0_SCL_M2: J5.84 U8.6 | length 5634.8
  TOP w6: v1(1320,264.37) 1367.2,311.57 2581.2,311.57 2609.8,340.17 2609.8,588.17 2585.82,612.14 J5.84@2585.82,722.26
  ART03 w5.5: v1(221,3097.16) 157,3033.16 157,2536.37 143,2522.37 143,2444.37 129,2430.37 129,2085.37 143,2071.37 143,1426.37 241,1328.37 241,468.37 277.5,431.87 313.13,431.87 405.63,339.37 705,339.37 720,324.37 1260,324.37 v1(1320,264.37)
  BOTTOM w6: v1(221,3097.16) 231,3087.16 U8.6@261.61,3087.16
I2C0_SDA_M2: J5.86 U8.5 | length 5690.2
  TOP w6: v1(1355,264.37) 1385,294.37 2591.2,294.37 2626.4,329.57 2626.4,593.97 2601.57,618.8 J5.86@2601.57,722.26
  ART03 w5.5: v1(221,3139.37) 240,3120.37 240,3087.37 175,3022.37 175,2534.37 157,2516.37 157,1442.37 260,1339.37 260,479.37 281,458.37 320.54,458.37 413.54,365.37 924,365.37 940,349.37 1260.46,349.37 1320.46,289.37 1330,289.37 v1(1355,264.37)
  BOTTOM w6: v1(221,3139.37) 221,3125.37 233.61,3112.76 U8.5@261.61,3112.76
I2C1_SCL_M2: J5.88 J23.6 R163.2 R230.2 U39.6 | length 8059.6
  TOP w6: J5.88@2617.32,722.26 2617.32,627.05 2642.2,602.17 2642.2,416.97 2739.8,319.37 3200,319.37 v1(3210,309.37)
  BOTTOM w6: U39.6@905.16,2411.73 905.16,2333.89 R230.2@910,2329.05 885.8,2304.85 885.8,2168.17 699.8,1982.17 699.8,1182.33 731.55,1150.57 1114.8,1150.57 1177,1088.37 1177,1022.37 1225,974.37 1225,899.37 1162.4,836.77 1162.4,626.97 1241.5,547.87 1241.5,449.87 1280,411.37 1280,142.66 1344.29,78.37 3084,78.37 3105,99.37 3105,289.37 3125,309.37 v1(3210,309.37) 3230,329.37 4826.72,329.37 4896.6,399.25 4896.6,477.45 R163.2@4875,499.05 4875,625.77 4948.05,698.82 J23.6@4978.61,698.82
I2C1_SDA_M2: J5.90 J23.5 R161.2 R231.2 U39.7 | length 8149.6
  TOP w6: J5.90@2633.07,722.26 2633.07,634.7 2656.6,611.17 2656.6,429.97 2747.2,339.37 3220,339.37 v1(3250,309.37)
  BOTTOM w6: U39.7@885.47,2411.73 885.47,2349.52 R231.2@865,2329.05 828,2292.05 828,2239.37 855,2212.37 855,2163.37 682.6,1990.97 682.6,1175.2 724.43,1133.37 1102,1133.37 1157,1078.37 1157,1012.37 1200,969.37 1200,909.37 1140,849.37 1140,614.37 1219,535.37 1219,437.37 1260,396.37 1260,134.37 1338,56.37 3092,56.37 3130,94.37 3130,279.37 3139.2,288.57 3229.2,288.57 v1(3250,309.37) 4835,309.37 4945,419.37 4945,474.05 R161.2@4920,499.05 4892.2,526.85 4892.2,621.57 4949.76,679.13 J23.5@4978.61,679.13
I2C2_SCL_M4: J5.54 J19.9 J21.6 R148.2 | length 5909.7
  TOP w6: v1(2295.63,494.37) 2295.63,570 2349.6,623.97 J5.54@2349.6,722.26 ; v1(5075,1569.37) 5144,1569.37 5166,1591.37 5166,2000.37 5181,2015.37 5181,2241.37 5163,2259.37 v1(5163,2268.37)
  ART03 w5.5: v1(2295.63,494.37) 2315,475 2315,424.37 2335,404.37 2955,404.37 2970,419.37 3025,419.37 3056,388.37 4124,388.37 4215,479.37 4755,479.37 v1(4800,434.37)
  BOTTOM w5.2: J19.9@4980.62,2765.53 5007.53,2765.53 5027.69,2745.37 5045.04,2745.37 5067.29,2767.62 5082.71,2767.62 5105.96,2744.37 ; v1(5163,2268.37) 5182,2287.37
  BOTTOM w6: v1(4800,434.37) 4834.2,468.57 4834.2,835.17 4792.8,876.57 4792.8,1477.8 4880.17,1565.17 4978.4,1565.17 J21.6@4978.61,1564.96 5070.59,1564.96 v1(5075,1569.37) ; R148.2@4864.68,2814.37 4913.52,2765.53 J19.9@4980.62,2765.53 ; 5105.96,2744.37 5145,2744.37 5182,2707.37 5182,2287.37
I2C2_SDA_M4: J5.56 J19.10 J21.5 R152.2 | length 5878.8
  TOP w6: v1(2335,494.37) 2335,579.37 2365.35,609.72 J5.56@2365.35,722.26 ; v1(5035,1529.37) 5055,1549.37 5181,1549.37 5194.21,1562.58 5194.21,2259.16 5185.84,2267.53 5185.84,2284.9 v1(5163,2307.74)
  ART03 w5.5: v1(2335,494.37) 2335,434.37 2345,424.37 2945,424.37 2960,439.37 3040,439.37 3073,406.37 4112,406.37 4205,499.37 4770,499.37 v1(4835,434.37)
  BOTTOM w5.2: J19.10@4980.62,2745.84 5006.53,2745.84 5023,2729.37 5039,2729.37 5063.95,2704.42 5083.75,2704.42 5099.69,2720.37
  BOTTOM w6: v1(4835,434.37) 4850.2,449.57 4850.2,843.5 4810,883.7 4810,1474.37 4885,1549.37 4935,1549.37 4939.1,1545.27 J21.5@4978.61,1545.27 5019.1,1545.27 v1(5035,1529.37) ; R152.2@4864.68,2774.37 4880,2774.37 4908.53,2745.84 J19.10@4980.62,2745.84 ; 5099.69,2720.37 5135.62,2720.37 5163,2692.99 v1(5163,2307.74)
I2C5_SCL_M3: J5.92 J20.9 J22.6 R150.2 | length 4905.8
  TOP w6: J5.92@2648.82,722.26 2648.82,648.75 2675.4,622.17 2675.4,432.97 2749,359.37 v1(2975,359.37) ; v1(4845,1969.37) 4851,1969.37 4920,1900.37 4920,1826.06 4925.2,1820.86 J22.6@4978.61,1820.86 ; v1(4895,2474.37) 4930.27,2509.64 J20.9@4980.62,2509.64
  BOTTOM w6: v1(2975,359.37) 2994,378.37 4568.6,378.37 4580,389.77 4580,849.48 4680.6,950.08 4680.6,1378.14 4630.1,1428.64 4630.1,1785.47 4814,1969.37 v1(4845,1969.37) 4822,1992.37 4822,2436.69 R150.2@4864.68,2479.37 4890,2479.37 v1(4895,2474.37)
I2C5_SDA_M3: J5.94 J20.10 J22.5 R154.2 | length 4916.7
  TOP w6: J5.94@2664.57,722.26 2664.57,658 2692.6,629.97 2692.6,441.57 2754.8,379.37 2995,379.37 v1(3015,359.37) ; v1(4885,1969.37) 4940,1914.37 4940,1845.75 4945.2,1840.55 J22.5@4978.61,1840.55 ; v1(4895,2519.37) 4904.96,2529.33 J20.10@4980.62,2529.33
  BOTTOM w6: v1(3015,359.37) 4580,359.37 4597.2,376.57 4597.2,842.35 4697.8,942.95 4697.8,1385.27 4647.9,1435.16 4647.9,1777.73 4805.54,1935.37 4851,1935.37 v1(4885,1969.37) 4865,1989.37 4865,2396.37 4920,2451.37 4920,2494.37 v1(4895,2519.37) R154.2@4864.68,2519.37
I2C7_SCL_M0_CODEC: J5.77 R185.2 R197.1 | length 2290.7
  TOP w6: v1(2250,1209.37) 2520,1209.37 2538.58,1190.79 J5.77@2538.58,826.59
  BOTTOM w6: R197.1@1985,2629.05 2003,2629.05 2015,2617.05 2015,2554.37 2110,2459.37 2110,2389.69 R185.2@2135.32,2364.37 2160.32,2339.37 2207.4,2339.37 2219.4,2327.37 2219.4,1442.97 2315,1347.37 2315,1259.37 2265,1209.37 v1(2250,1209.37)
I2C7_SDA_M0_CODEC: J5.75 R188.2 R198.1 | length 2416
  TOP w6: v1(2250,1159.37) 2280,1189.37 2508,1189.37 2522.83,1174.54 J5.75@2522.83,826.59
  BOTTOM w6: R198.1@1945,2629.05 1965.8,2649.85 2018,2649.85 2030,2637.85 2030,2564.37 2135.32,2459.05 R188.2@2135.32,2409.37 2156.12,2388.57 2225,2388.57 2236.6,2376.97 2236.6,1452.77 2332.2,1357.17 2332.2,1241.57 v1(2250,1159.37)
I2C8_SCL_M2: J5.96 J24.6 R164.2 | length 3387.3
  TOP w6: J5.96@2680.31,722.26 2680.31,667.06 2706.4,640.97 2706.4,454.77 2761.8,399.37 v1(2975,399.37) ; v1(4560,440.77) 4746.4,440.77 4804.68,499.05 R164.2@4875,499.05 4875.99,499.05 4906.31,529.37 4924,529.37 4979,584.37 5010,584.37 5045,619.37 5140.68,619.37 5165,643.7 5165,969.17 5154.8,979.37 5060,979.37 5035.35,954.72 J24.6@4978.61,954.72
  BOTTOM w6: v1(2975,399.37) 2995,419.37 4538.6,419.37 v1(4560,440.77)
I2C8_SDA_M2: J5.98 J24.5 R162.2 | length 3509
  TOP w6: J5.98@2696.06,722.26 2696.06,671.71 2723,644.77 2723,461.57 2765.2,419.37 2995,419.37 v1(3015,399.37) ; v1(4560,397.37) 4928,397.37 4950,419.37 4950,469.05 R162.2@4920,499.05 4988.12,567.17 5017.12,567.17 5049.32,599.37 5145,599.37 5185,639.37 5185,973.5 5161.93,996.57 5049.36,996.57 5027.2,974.41 J24.5@4978.61,974.41
  BOTTOM w6: v1(3015,399.37) 4558,399.37 v1(4560,397.37)
I2C_ADDR_SET: R200.2 U33.26 | length 110.1
  BOTTOM w6: R200.2@1905,2589.69 1930,2564.69 1930,2529.37 1937.72,2521.65 U33.26@1937.72,2493.11
I2S0_LRCK: J5.85 R194.1 | length 1877.8
  TOP w6: v1(2210,1259.37) 2232,1281.37 2576.87,1281.37 2601.57,1256.67 J5.85@2601.57,826.59
  BOTTOM w6: R194.1@2015,2199.69 2015,2134.37 2143,2006.37 2143,1405.37 2229,1319.37 2229,1278.37 v1(2210,1259.37)
I2S0_MCLK: J5.81 R190.1 | length 1960
  TOP w6: v1(2210,1209.37) 2235,1234.37 2531,1234.37 2559,1206.37 2559,914.37 2570.08,903.29 J5.81@2570.08,826.59
  BOTTOM w6: R190.1@2174.68,2314.37 2200,2289.05 2200,1434.37 2295,1339.37 2295,1269.37 2260,1234.37 2235,1234.37 v1(2210,1209.37)
I2S0_SCLK: J5.83 R191.1 | length 1780.5
  TOP w6: v1(2250,1259.37) 2565,1259.37 2577,1247.37 2577,921.37 2585.82,912.54 J5.83@2585.82,826.59
  BOTTOM w6: R191.1@2095,2199.69 2095,2119.37 2180,2034.37 2180,1424.37 2273.6,1330.77 2273.6,1282.97 v1(2250,1259.37)
I2S0_SDI0: J5.89 R195.1 | length 1962.8
  TOP w6: v1(2210,1309.37) 2235,1334.37 2643,1334.37 2667,1310.37 2667,1102.37 2646,1081.37 2646,918.37 2633.07,905.44 J5.89@2633.07,826.59
  BOTTOM w6: R195.1@1975,2199.69 1975,2145.37 2122,1998.37 2122,1397.37 v1(2210,1309.37)
I2S0_SDO0: J5.87 R193.1 | length 1820.5
  TOP w6: v1(2250,1309.37) 2601,1309.37 2628,1282.37 2628,928.37 2617.32,917.69 J5.87@2617.32,826.59
  BOTTOM w6: R193.1@2055,2199.69 2055,2126.57 2161,2020.57 2161,1412.91 2250,1323.91 v1(2250,1309.37)
LCD0_BL_PWM: J6.85 J19.13 | length 3144.5
  TOP w6: v1(2599.37,2581.37) 2601.57,2579.17 J6.85@2601.57,2543.51 ; v1(3002.17,2875.31) 3023.31,2854.17 3175,2854.17 3235.8,2793.37 3381,2793.37 3455.37,2867.74 3586,2867.74 v1(3605,2848.74) ; v1(4917.37,2980.37) 4916,2979 4916,2703.37 v1(4935,2684.37)
  ART03 w5.5: v1(3605,2848.74) 3615.63,2859.37 3781.4,2859.37 3823.2,2817.57 4632.7,2817.57 4668.9,2853.77 4808.13,2853.77 4868.73,2914.37 4900,2914.37 4917.37,2931.74 v1(4917.37,2980.37)
  BOTTOM w6: v1(2599.37,2581.37) 2599.37,2543.37 2619.37,2523.37 2743,2523.37 2755,2535.37 2755,2606.34 2979,2830.34 2979,2852.13 v1(3002.17,2875.31) ; v1(4935,2684.37) 4937.42,2686.79 J19.13@4980.62,2686.79
LCD0_PWR_EN: J5.59 R156.1 | length 5272
  TOP w6: v1(2366.26,964.37) 2396.85,933.78 J5.59@2396.85,826.59 ; v1(5145,2014.37) 5163,2032.37 5163,2226.37 5144,2245.37 5144,2942.37 5155,2953.37 R156.1@5155,3144.69
  ART03 w5.5: v1(2366.26,964.37) 2385.26,983.37 2385.52,983.37 2471.52,1069.37 4043,1069.37 4055,1081.37 4055,1479.37 4075,1499.37 4523.03,1499.37 4683.03,1339.37 5040,1339.37 5130,1429.37 5130,1914.37 5091.74,1952.63 5091.74,2006.11 5100,2014.37 v1(5145,2014.37)
LCD0_RST: J5.66 J19.15 | length 5299.3
  TOP w6: v1(2420,449.37) 2440.37,449.37 2460,469 2460,619.37 2444.09,635.28 J5.66@2444.09,722.26
  ART03 w5.5: v1(2420,449.37) 2940,449.37 2950,459.37 3055,459.37 3089,425.37 4096,425.37 4190,519.37 5010,519.37 5087.5,596.87 5087.5,842.87 5150,905.37 5150,1184.01 5167,1201.01 5167,1942.37 v1(5145,1964.37)
  BOTTOM w6: J19.15@4980.62,2647.42 5046.95,2647.42 5062,2632.37 5082.12,2632.37 5109.56,2604.93 5121,2604.93 5143,2582.93 5143,2198.37 5165,2176.37 5165,1984.37 v1(5145,1964.37)
LCD1_BL_PWM: J6.87 J20.13 | length 3176.8
  TOP w6: v1(2599.37,2620.74) 2618.37,2601.74 2618.37,2573.5 2617.32,2572.45 J6.87@2617.32,2543.51 ; v1(3002.17,2835.94) 3171.03,2835.94 3230.74,2776.23 3388.1,2776.23 3460.61,2848.74 v1(3565.63,2848.74) ; v1(4875.6,2894.37) 4875,2893.77 4875,2689.37 4896.4,2667.97 4896.4,2628.38 4936.4,2588.38 J20.13@4980.62,2588.38
  ART03 w5.5: v1(3565.63,2848.74) 3586,2828.37 3618,2828.37 3631,2841.37 3772,2841.37 3808.8,2804.57 4639,2804.57 4671,2836.57 4817.8,2836.57 v1(4875.6,2894.37)
  BOTTOM w6: v1(2599.37,2620.74) 2580,2601.37 2580,2526.37 2600,2506.37 2760,2506.37 2772,2518.37 2772,2606.37 3001.57,2835.94 v1(3002.17,2835.94)
LCD1_PWR_EN: J5.61 R155.1 | length 3717.5
  TOP w6: v1(2405.63,964.37) 2412.6,957.4 J5.61@2412.6,826.59 ; R155.1@4674.68,1954.37 4674.68,1334.69 4695,1314.37 v1(4755,1314.37)
  ART03 w5.5: v1(2405.63,964.37) 2489.63,1048.37 4059,1048.37 4080,1069.37 4080,1470.37 4092,1482.37 4522,1482.37 4690,1314.37 v1(4755,1314.37)
LCD1_RST: J6.60 J20.15 | length 3182.1
  TOP w6: J6.60@2396.84,2677.37 2396.84,2789.8 2466.68,2859.64 v1(2466.68,2889.37) ; v1(4875,2934.37) 4896.4,2912.97 4896.4,2696.66 4915,2678.07 4915,2636.08 4926.71,2624.37 4977.24,2624.37 J20.15@4980.62,2627.75
  ART03 w5.5: v1(2466.68,2889.37) 2488,2910.69 2488,2938.37 2499,2949.37 2712,2949.37 2747,2914.37 3031,2914.37 3053,2892.37 3497,2892.37 3538,2933.37 3802,2933.37 3819,2916.37 4158.8,2916.37 4204.6,2870.57 4604,2870.57 4615,2881.57 4615,2902.12 4626,2913.12 4831.12,2913.12 4852.37,2934.37 v1(4875,2934.37)
MDIN0_PHY: J15.3 U14.2 | length 1215.1
  TOP w4.2: v1(4330.5,2959.37) 4330.5,2957.37 4321.55,2948.42 4321.55,2939.22 ccw(c4323.91,2939.22) 4323.91,2936.86 cw(c4323.91,2932.98) 4327.79,2932.98 4327.79,2923.93 cw(c4323.91,2923.93) 4323.91,2920.05 ccw(c4323.91,2917.69) 4321.55,2917.69 4321.55,2908.35 4330.53,2899.37 4343.26,2899.37 ccw(c4343.26,2903.09) 4346.98,2903.09 cw(c4351.78,2903.09) 4351.78,2907.89 4358.98,2907.89 cw(c4358.98,2903.09) 4363.78,2903.09 ccw(c4367.5,2903.09) 4367.5,2899.37 4557.5,2899.37 4617,2958.87 4643.85,2958.87 4675.54,2990.56 4684.74,2990.56 ccw(c4684.74,2993.68) 4687.86,2993.68 cw(c4690.99,2993.68) 4690.99,2996.81 4701.54,2996.81 cw(c4701.54,2993.68) 4704.66,2993.68 ccw(c4707.79,2993.68) 4707.79,2990.56 4727.83,2990.56 4776.39,3039.12 4776.39,3120.77 4766.4,3130.76 4762.71,3132.61 4757.34,3130.82 J15.3@4731.49,3079.13
  BOTTOM w4.2: v1(4330.5,2959.37) 4323.1,2951.97 4323.1,2576.55 4337.53,2562.12 4337.53,2531.87 4339.88,2529.51 U14.2@4339.88,2512.8
MDIN1_PHY: J15.7 U14.5 | length 1232.4
  TOP w4.2: v1(4394.63,2959.37) 4387.37,2952.11 4387.37,2932 4392.6,2926.77 4546.15,2926.77 4605.65,2986.27 4632.5,2986.27 4673.8,3027.57 4673.8,3104.73 4623.8,3154.73 4623.8,3211.26 4616.3,3218.76 4565.13,3218.76 4531.49,3185.12 J15.7@4531.49,3079.13
  BOTTOM w4.2: U14.5@4387.13,2512.8 4387.13,2530.56 4384.46,2533.24 4384.46,2949.2 v1(4394.63,2959.37)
